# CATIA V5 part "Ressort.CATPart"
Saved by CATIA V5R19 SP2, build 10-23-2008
Part number: Ressort
Bounding box of the stored display mesh (mm): x -22 to 21.999, y -673 to -629.002, z 295 to 455
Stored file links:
  C:\Users\Pauline\Desktop\CFAO_Catia\Compte_rendu\pmayet_assemblage_animation4\Ressort.CATPart
  C:\Users\Pauline\Desktop\CFAO_Catia\Compte_rendu\pmayet_assemblage_animation4\pmayet_assemblage_animation.CATProduct
  C:\Users\Pauline\Desktop\CFAO_Catia\Compte_rendu\pmayet_assemblage_animation4\Squelette_amortisseur.CATPart
  C:\Users\Pauline\Desktop\Projet Catia\Assemblage\Haut_amortisseur.CATPart
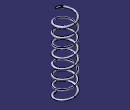
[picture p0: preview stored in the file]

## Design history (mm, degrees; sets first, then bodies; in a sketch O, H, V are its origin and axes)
Parameters
  Rayon_tige_amortisseur = 8 mm
  Hauteur_amortiseur = 80 mm
  `Raton_hélice` = 2 mm
Set1
  Plane1: linked copy from another document
  Point1 "Point.21_début_ressort": linked copy from another document
  DatumCurve1: linked copy from another document
  Plane2 to Plane4: linked copy from another document
Set2
  Extrude1: Element1 Sketch3, Lim1 50, Lim2 50, Direction Plane2
  Extrude2: Element1 Sketch2, Lim1 50, Lim2 50, Direction Plane2
Body1 (main body)
  Sketch1 on Plane1, origin (71.0113, 0, 8.8228), H (0, -1, 0), V (-0.1572, 0, 0.9876)
    circle A1 centre (671, 451.7927) radius 2
    point P1 (671, 451.7927)
    reference projected point E1 (671, 451.7927) from Point1
    distance A1 P1 = 2 {= `Raton_hélice`}
    coincidence: P1 E1
  Rib1: profile Sketch1, centre curve DatumCurve1
  Sketch2 on Plane2, origin (0, 0, 0), H (0, 1, 0), V (0, 0, 1)
    line L1 (-701, 295) -> (-601, 295)
    point P1 (-701, 295)
    reference projected line E1 (-701, 455) -> (-601, 455) from Sketch3
    reference projected line E2 (-701, 455) -> (-601, 455) from Sketch3
    reference intersected line E3 through (-651, 0) direction (0, 1) from Plane4
    distance E1 L1 = 160 {= Hauteur_amortiseur *2}
    length L1 = 100
    distance E3 P1 = 50
    parallelism: E2 L1
  Sketch3 on Plane2, origin (0, 0, 0), H (0, 1, 0), V (0, 0, 1)
    line L1 (-701, 455) -> (-601, 455)
    point P1 (-701, 455)
    reference intersected line E1 through (0, 455) direction (-1, 0) from Plane3
    reference intersected line E2 through (0, 455) direction (-1, 0) from Plane3
    reference intersected line E3 through (-651, 0) direction (0, 1) from Plane4
    distance E1 L1 = 0
    length L1 = 100
    distance P1 E3 = 50
    parallelism: E2 L1
  Split1: SplitPlane Extrude1
  Split2: SplitPlane Extrude2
